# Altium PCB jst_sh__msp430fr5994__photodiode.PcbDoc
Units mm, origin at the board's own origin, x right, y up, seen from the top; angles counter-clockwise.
Board outline 56 x 30 mm, 2 copper layers (Top, Bottom), stack 0 mm thick; 17 components, 9 nets, 94 pads, 27 vias.
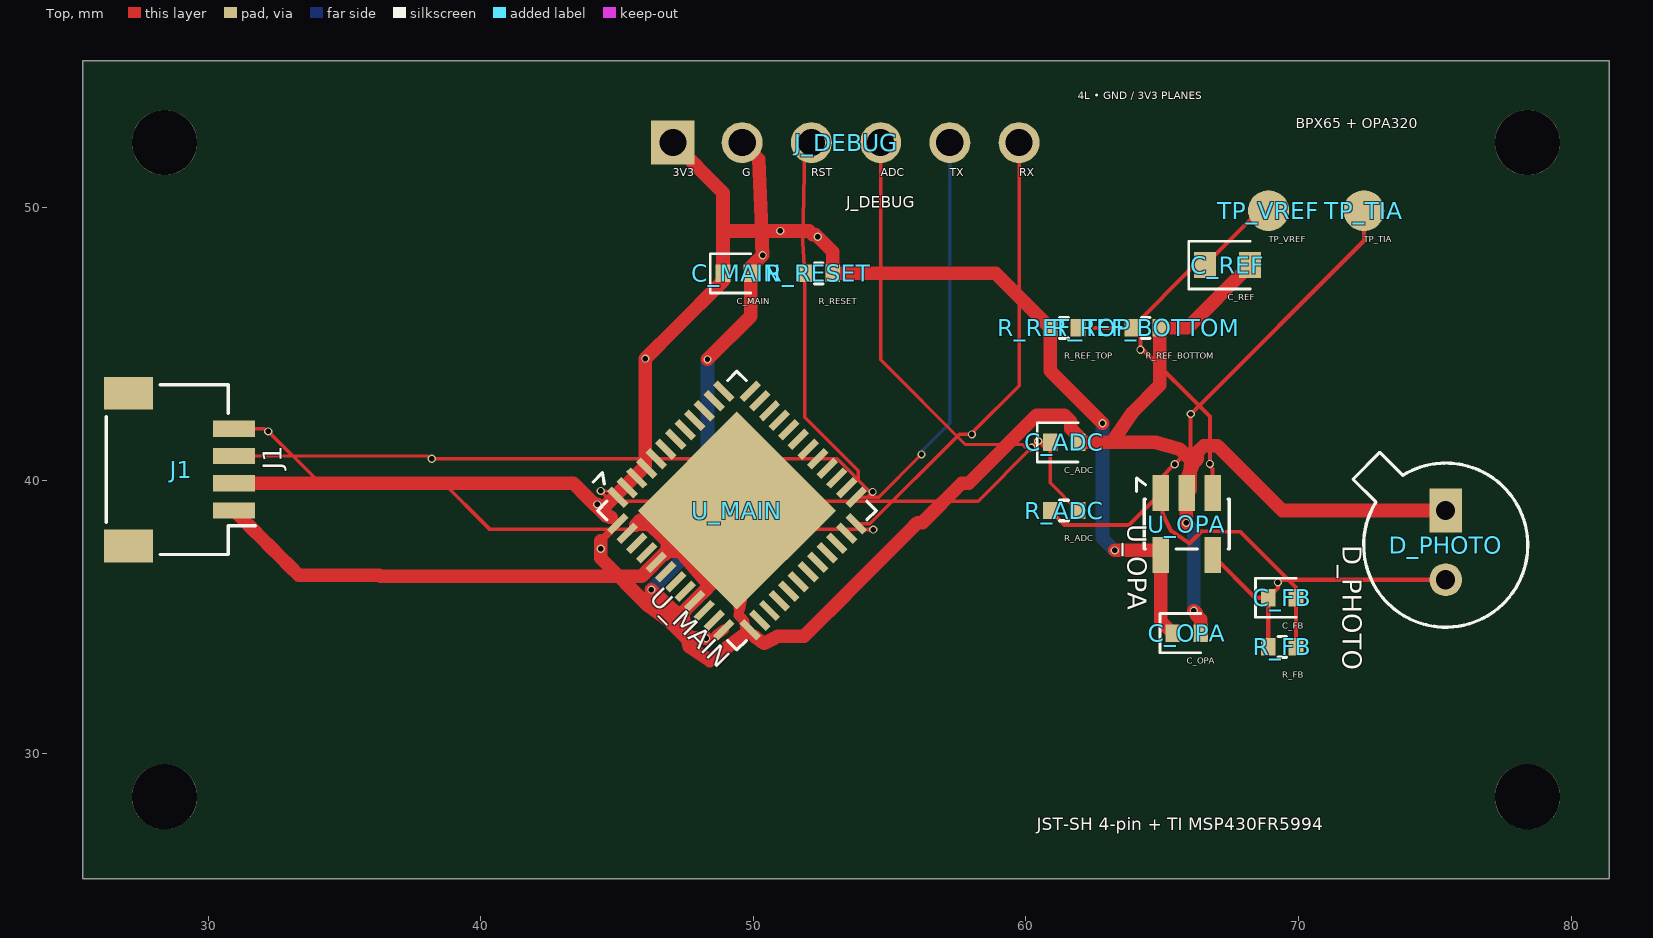
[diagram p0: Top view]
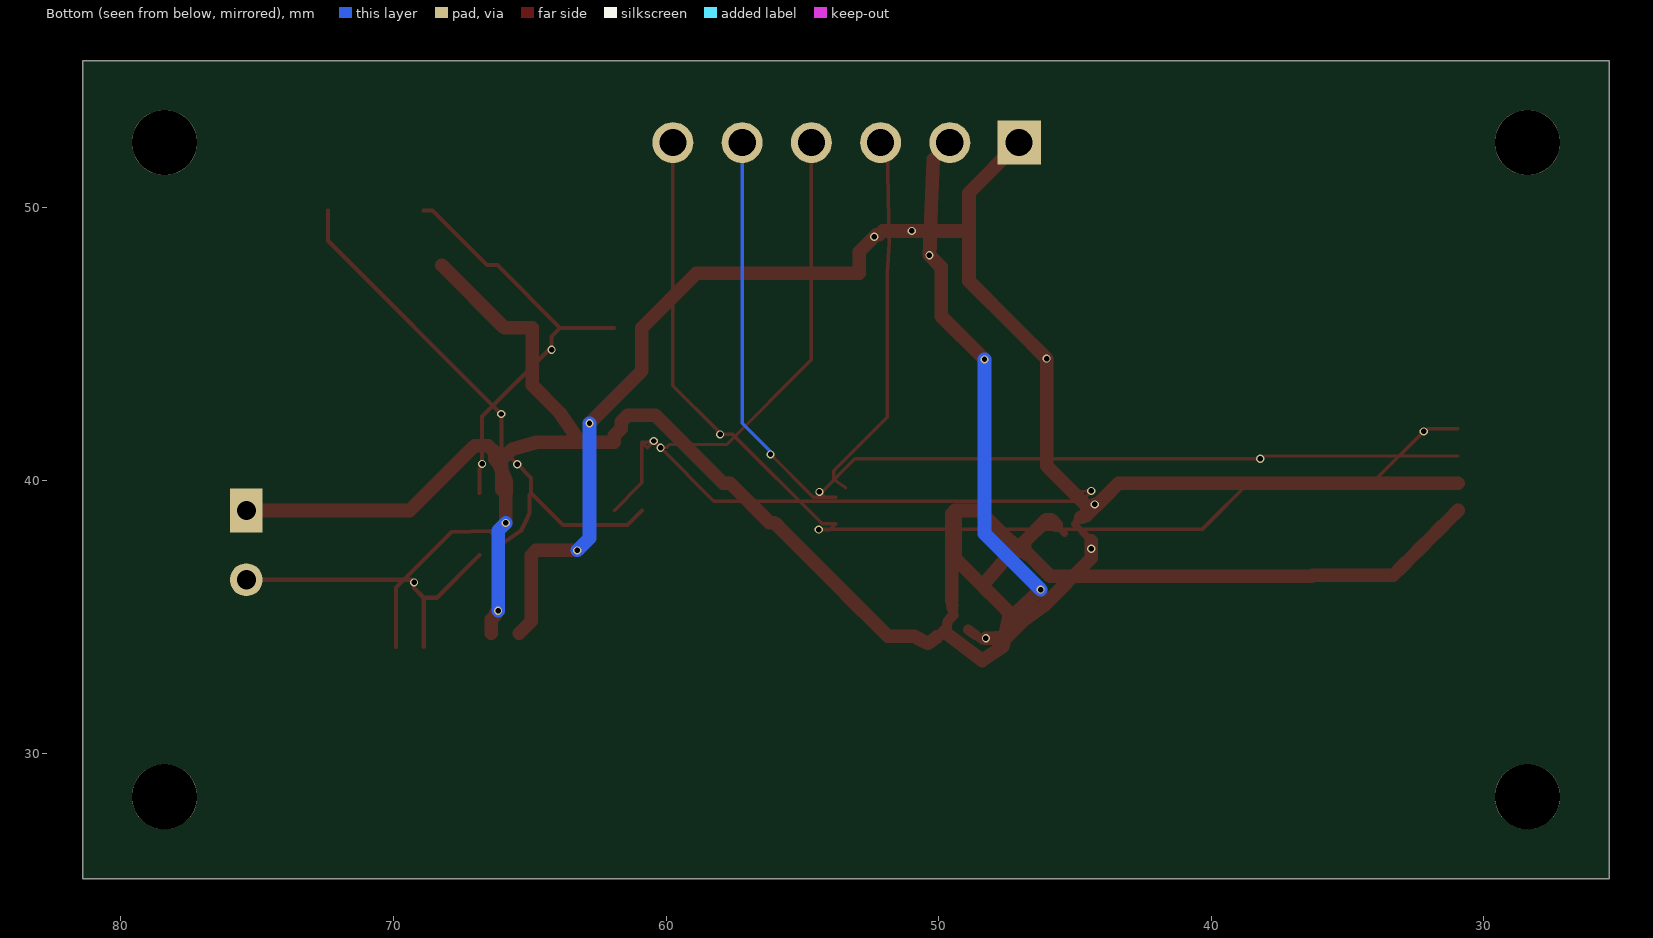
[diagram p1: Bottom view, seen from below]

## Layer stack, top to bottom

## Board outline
25.4,55.4 81.4,55.4 81.4,25.4 25.4,25.4

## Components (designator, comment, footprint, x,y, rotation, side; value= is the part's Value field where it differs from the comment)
C_ADC "" TSCIRCUIT-1.5600x0.6400mm 61.4,41.4 r0 top
C_FB "" TSCIRCUIT-1.5600x0.6400mm 69.4,35.7 r0 top
C_MAIN "" TSCIRCUIT-1.5600x0.6400mm 49.4,47.6 r0 top
C_OPA "" TSCIRCUIT-1.5600x0.6400mm 65.9,34.4 r0 top
C_REF "" TSCIRCUIT-2.4500x0.9500mm 67.4,47.9 r0 top
D_PHOTO "" TSCIRCUIT-1.2000x3.9400mm 75.4,37.73 r270 top
J1 "" TSCIRCUIT-5.5500x6.8000mm 28.95,40.4 r90 top
J_DEBUG "" TSCIRCUIT-14.2000x1.5000mm 53.4,52.4 r0 top
R_ADC "" TSCIRCUIT-1.5600x0.6400mm 61.4,38.9 r0 top
R_FB "" TSCIRCUIT-1.5600x0.6400mm 69.4,33.9 r0 top
R_REF_BOTTOM "" TSCIRCUIT-1.5600x0.6400mm 64.4,45.6 r0 top
R_REF_TOP "" TSCIRCUIT-1.5600x0.6400mm 61.4,45.6 r0 top
R_RESET "" TSCIRCUIT-1.5600x0.6400mm 52.4,47.6 r0 top
TP_TIA "" TSCIRCUIT-1.5000x1.5000mm 72.4,49.9 r0 top
TP_VREF "" TSCIRCUIT-1.5000x1.5000mm 68.9,49.9 r0 top
U_MAIN "" TSCIRCUIT-9.5459x9.5459mm 49.4,38.9 r315 top
U_OPA "" TSCIRCUIT-2.5000x3.6000mm 65.9,38.4 r270 top

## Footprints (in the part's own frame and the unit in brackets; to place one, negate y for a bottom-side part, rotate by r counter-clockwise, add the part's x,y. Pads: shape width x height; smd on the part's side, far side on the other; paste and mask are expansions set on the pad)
TSCIRCUIT-1.2000x3.9400mm [mm]
  rect 1.6x1.2 hole 0.7: 1(-1.17,0)
  round 1.2 hole 0.7: 2(1.37,0)
  silkscreen extent -3.3,-3.4 3.11,3.01
TSCIRCUIT-1.5000x1.5000mm [mm]
  round 1.5 smd: 1(0,0)
TSCIRCUIT-1.5600x0.6400mm [mm]
  rect 0.54x0.64 smd: 1(-0.51,0) 2(0.51,0)
  silkscreen extent -0.98,-0.72 0.51,0.72
TSCIRCUIT-2.4500x0.9500mm [mm]
  rect 0.8x0.95 smd: 1(-0.825,0) 2(0.825,0)
  silkscreen extent -1.43,-0.87 0.82,0.87
TSCIRCUIT-2.5000x3.6000mm [mm]
  rect 1.325x0.6 smd: 1(-1.138,-0.95) 2(-1.138,0) 3(-1.138,0.95) 4(1.137,0.95) 5(1.137,-0.95)
  silkscreen extent -1.69,-1.84 0.91,1.56
TSCIRCUIT-5.5500x6.8000mm [mm]
  rect 1.2x1.8 smd: 1(-2.8,1.875) 1(2.8,1.875)
  rect 0.6x1.55 smd: 1(-1.5,-2) 2(-0.5,-2) 3(0.5,-2) 4(1.5,-2)
  silkscreen extent -3.11,-2.77 3.11,2.69
TSCIRCUIT-9.5459x9.5459mm [mm]
  rect 0.875x0.25 smd: 1(-3.438,-2.75) 2(-3.438,-2.25) 3(-3.437,-1.75) 4(-3.437,-1.25) 5(-3.438,-0.75) 6(-3.438,-0.25) 7(-3.437,0.25) 8(-3.437,0.75) 9(-3.438,1.25) 10(-3.438,1.75) 11(-3.437,2.25) 12(-3.437,2.75) 25(3.438,2.75) 26(3.438,2.25) 27(3.438,1.75) 28(3.438,1.25) 29(3.438,0.75) 30(3.438,0.25) 31(3.438,-0.25) 32(3.438,-0.75) 33(3.438,-1.25) 34(3.438,-1.75) 35(3.438,-2.25) 36(3.438,-2.75)
  rect 0.25x0.875 smd: 13(-2.75,3.437) 14(-2.25,3.437) 15(-1.75,3.437) 16(-1.25,3.438) 17(-0.75,3.437) 18(-0.25,3.437) 19(0.25,3.437) 20(0.75,3.438) 21(1.25,3.437) 22(1.75,3.437) 23(2.25,3.437) 24(2.75,3.438) 37(2.75,-3.438) 38(2.25,-3.438) 39(1.75,-3.438) 40(1.25,-3.438) 41(0.75,-3.438) 42(0.25,-3.438) 43(-0.25,-3.438) 44(-0.75,-3.438) 45(-1.25,-3.438) 46(-1.75,-3.438) 47(-2.25,-3.438) 48(-2.75,-3.438)
  rect 5.15x5.15 smd: 49(0,0)
  silkscreen extent -4.47,-3.61 3.61,3.61
TSCIRCUIT-14.2000x1.5000mm [mm]
  rect 1.6x1.6 hole 1: 1(-6.35,0)
  round 1.5 hole 1: 2(-3.81,0) 3(-1.27,0) 4(1.27,0) 5(3.81,0) 6(6.35,0)

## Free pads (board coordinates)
  round 2.4 hole 2.4 unplated: NPTH-1(28.4,28.4) NPTH-2(78.4,52.4) NPTH-3(78.4,28.4) NPTH-4(28.4,52.4)

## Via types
v1: diameter 0.3, hole 0.2, Top to Bottom, 27 vias

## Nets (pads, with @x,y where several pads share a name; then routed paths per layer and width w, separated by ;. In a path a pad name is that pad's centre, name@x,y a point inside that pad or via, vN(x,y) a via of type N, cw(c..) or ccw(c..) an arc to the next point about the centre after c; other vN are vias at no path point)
ADC_IN: C_ADC.1 J_DEBUG.4 R_ADC.2 U_MAIN.1 | length 37
  Top w0.12: U_MAIN.1 44.811,39.6 v1(44.406,39.621) 44.412,39.588 44.426,39.588 44.771,39.244 44.783,39.244 58.244,39.244 v1(60.2,41.2) 60.217,41.217 60.4,41.4 C_ADC.1 ; J_DEBUG.4 54.67,44.429 57.777,41.322 59.878,41.322 59.983,41.217 60.183,41.217 v1(60.45,41.45) 60.69,41.2 C_ADC.1 ; R_ADC.2 60.89,39.92 C_ADC.1
GND: C_ADC.2 C_MAIN.2 C_OPA.2 C_REF.2 D_PHOTO.1 J1.1@30.95,38.9 J_DEBUG.2 R_REF_BOTTOM.2 U_MAIN.36 U_MAIN.40 U_MAIN.44 U_MAIN.47 U_MAIN.49 U_OPA.2 | length 113.1
  Top w0.25: U_MAIN.44@46.483,37.044 U_MAIN.44 ; 47.544,35.276 U_MAIN.40 U_MAIN.40@48.163,35.895 ; U_MAIN.36@49.631,34.888 U_MAIN.36@49.65,34.869 ; U_MAIN.36@49.786,34.449 U_MAIN.36 ; U_MAIN.44 46.748,37.309 U_MAIN.44 ; U_MAIN.47 45.688,38.37 U_MAIN.47
  Top w0.34: U_MAIN.44@46.483,37.044 46.483,37.067 U_MAIN.44@46.764,37.294
  Top w0.375: 49.492,35.332 49.462,35.056 49.631,34.888 ; U_MAIN.36@49.65,34.869 49.728,34.494 49.769,34.465
  Top w0.4: 49.769,34.465 U_MAIN.36@50.064,34.259
  Top w0.45: 49.492,35.332 U_MAIN.49@49.521,35.607
  Top w0.5: J1.1@30.95,38.9 31.289,38.561 31.628,38.222 31.967,37.883 32.306,37.544 32.644,37.206 32.983,36.867 33.322,36.528 33.815,36.528 34.309,36.528 34.802,36.528 35.295,36.528 35.788,36.528 36.281,36.528 36.325,36.483 45.9,36.483 46.838,37.421 46.838,37.775 46.046,38.567 45.9,38.567 45.885,38.567 45.688,38.37 45.744,38.426 45.744,38.431 46.025,38.525 46.509,38.103 46.983,37.629 46.983,37.567 46.983,37.544 46.748,37.309 46.839,37.4 47.317,37.4 48.317,36.233 48.317,36.049 48.163,35.895 ; v1(46.261,36) 47.15,35.15 47.4,35.15 ; 46.764,37.294 47.096,37.563 47.521,37.907 47.852,38.238 48.183,38.569 48.514,38.9 48.957,38.9 U_MAIN.49 ; 47.544,35.276 47.418,35.15 47.4,35.15 ; v1(48.32,44.446) 49.91,46.036 C_MAIN.2 49.91,47.836 v1(50.338,48.263) 50.32,48.704 50.303,49.145 50.286,49.586 50.269,50.027 50.252,50.467 50.234,50.908 50.217,51.349 50.2,51.79 49.895,52.095 J_DEBUG.2 ; U_MAIN.49@49.521,35.607 49.521,36.06 49.521,36.513 49.521,36.966 49.521,37.419 49.521,37.872 49.521,38.326 49.521,38.779 U_MAIN.49 ; 49.786,34.449 48.4,33.4 47.65,33.9 47.4,35.15 ; U_MAIN.36@50.064,34.259 50.4,34.025 50.649,34.156 50.897,34.287 51.378,34.287 51.859,34.287 52.207,34.634 52.554,34.982 52.902,35.329 53.249,35.676 53.596,36.024 53.944,36.371 54.291,36.719 54.639,37.066 54.986,37.413 55.333,37.761 55.681,38.108 56.028,38.456 56.206,38.456 57.65,39.9 57.9,39.9 60.4,42.4 61.4,42.4 61.65,42.15 61.65,41.9 61.9,41.65 61.9,41.4 C_ADC.2 ; v1(65.88,38.445) 65.88,39.518 U_OPA.2 ; v1(66.164,35.22) 66.244,35.14 66.244,35.081 66.41,34.915 66.41,34.657 C_OPA.2 ; C_REF.2 65.925,45.6 R_REF_BOTTOM.2 64.91,43.5 63.918,42.508 63.15,41.4 C_ADC.2 ; D_PHOTO.1 69.4,38.9 67.025,41.275 66.525,41.275 66.275,41.025 66.275,40.775 66.025,40.525 66.025,39.662 U_OPA.2 ; 47.4,35.15 49.4,37.15 U_MAIN.49 ; C_ADC.2 64.741,41.4 64.746,41.405 65.65,41.15 66.15,40.65 65.875,39.97 65.875,39.562 U_OPA.2
  Bottom w0.5: v1(46.261,36) 48.32,38.059 v1(48.32,44.446) ; v1(65.88,38.445) 66.164,38.161 v1(66.164,35.22)
MAIN_RESET: J_DEBUG.3 R_RESET.1 U_MAIN.23 | length 13.8
  Top w0.12: J_DEBUG.3 51.89,52.16 51.817,48.727 R_RESET.1 51.89,42.319 53.846,40.363 53.846,40.07 53.838,40.03 53.837,40.029 U_MAIN.23
PD_SUM: C_FB.1 D_PHOTO.2 R_FB.1 U_OPA.4 | length 11.4
  Top w0.15: U_OPA.4 68.412,35.7 C_FB.1 ; R_FB.1 C_FB.1 ; D_PHOTO.2 69.36,36.36 69.277,36.277 69.259,36.277 v1(69.244,36.262) 69.246,36.056 C_FB.1
TIA_OUT: C_FB.2 R_ADC.1 R_FB.2 TP_TIA.1 U_OPA.1 | length 27.6
  Top w0.15: R_ADC.1 61.42,38.37 63.782,38.37 U_OPA.1 ; R_FB.2 C_FB.2 69.912,36.075 67.876,38.107 66.45,38.15 66,37.7 65.325,38.15 65.1,38.6 65.011,38.813 65.011,39.476 U_OPA.1 ; TP_TIA.1 72.4,48.797 66.123,42.52 v1(66.044,42.441) 66.044,41.186 65.519,40.661 v1(65.459,40.601) 64.95,40.092 U_OPA.1
UART_MAIN_RX: J1.4 J_DEBUG.6 U_MAIN.25 | length 42.7
  Top w0.13: J1.4 32.058,41.9 32.158,41.8 v1(32.203,41.8) 33.942,40.061 38.482,40.061 40.338,38.205 54.371,38.205 54.395,38.205 v1(54.4,38.2) 53.989,38.2 U_MAIN.25 54.275,38.414 57.552,41.691 v1(58.02,41.691) 58.1,41.771 58.1,41.833 59.75,43.483 J_DEBUG.6
UART_MAIN_TX: J1.3 J_DEBUG.5 U_MAIN.24 | length 39.6
  Top w0.12: J1.3 38.058,40.9 38.158,40.8 v1(38.2,40.8) 53.072,40.8 54.331,39.54 v1(54.376,39.585) 54.177,39.386 U_MAIN.24 54.598,39.386 v1(56.17,40.958)
  Bottom w0.12: v1(56.17,40.958) 56.184,40.972 56.184,41.075 57.21,42.101 J_DEBUG.5
VCC_3V3: C_MAIN.1 C_OPA.1 J1.2 J_DEBUG.1 R_REF_TOP.1 R_RESET.2 U_MAIN.37 U_MAIN.48 U_OPA.5 | length 68.9
  Top w0.25: 44.715,38.105 U_MAIN.48 ; U_MAIN.48 44.936,38.502 U_MAIN.48
  Top w0.275: 44.4,37.789 44.712,38.101 44.715,38.105 ; 44.589,38.711 44.728,38.711 44.936,38.502 44.781,38.658
  Top w0.325: v1(48.266,34.216) 48.4,34.15 U_MAIN.37@48.657,34.337
  Top w0.382: U_MAIN.37@48.657,34.337 U_MAIN.37
  Top w0.475: v1(44.274,39.124) 44.74,38.658
  Top w0.5: J1.2 31.434,39.9 31.918,39.9 32.403,39.9 32.887,39.9 33.371,39.9 33.855,39.9 34.339,39.9 43.4,39.9 43.9,39.4 44.589,38.711 ; v1(44.274,39.124) 44.4,38.998 44.4,38.9 46.041,40.541 v1(46.041,44.473) 46.082,44.514 46.433,44.865 46.784,45.216 47.135,45.567 47.486,45.918 47.837,46.269 48.188,46.62 48.539,46.971 48.89,47.322 C_MAIN.1 ; 44.4,37.789 v1(44.4,37.5) 44.4,37.15 46.15,35.4 46.89,34.871 47.21,34.551 47.53,34.231 47.898,34.223 v1(48.266,34.216) ; 44.74,38.658 44.781,38.658 ; J_DEBUG.1 48.89,50.56 C_MAIN.1 ; v1(62.81,42.101) 60.89,44.021 R_REF_TOP.1 58.89,47.6 R_RESET.2 52.91,48.396 v1(52.361,48.945) 52.287,49.019 52.177,49.019 52.04,49.156 51.689,49.156 51.337,49.156 v1(50.985,49.156) 48.89,49.156 C_MAIN.1 ; v1(63.256,37.438) 64.775,37.438 U_OPA.5 64.95,34.84 C_OPA.1
  Bottom w0.5: v1(62.81,42.101) 62.81,37.884 v1(63.256,37.438)
VREF_0V5: C_REF.1 R_REF_BOTTOM.1 R_REF_TOP.2 TP_VREF.1 U_OPA.3 | length 16.1
  Top w0.15: R_REF_TOP.2 R_REF_BOTTOM.1 ; U_OPA.3 66.85,40.418 66.766,40.502 66.766,40.593 v1(66.751,40.608) 66.751,42.342 64.25,44.843 64.243,44.843 v1(64.2,44.8) 64.2,45.29 R_REF_BOTTOM.1 ; TP_VREF.1 68.575,49.9 C_REF.1 66.19,47.9 R_REF_BOTTOM.1
pads on no net: J1.1@27.075,37.6 J1.1@27.075,43.2 U_MAIN.2 U_MAIN.3 U_MAIN.4 U_MAIN.5 U_MAIN.6 U_MAIN.7 U_MAIN.8 U_MAIN.9 U_MAIN.10 U_MAIN.11 U_MAIN.12 U_MAIN.13 U_MAIN.14 U_MAIN.15 U_MAIN.16 U_MAIN.17 U_MAIN.18 U_MAIN.19 U_MAIN.20 U_MAIN.21 U_MAIN.22 U_MAIN.26 U_MAIN.27 U_MAIN.28 U_MAIN.29 U_MAIN.30 U_MAIN.31 U_MAIN.32 U_MAIN.33 U_MAIN.34 U_MAIN.35 U_MAIN.38 U_MAIN.39 U_MAIN.41 U_MAIN.42 U_MAIN.43 U_MAIN.45 U_MAIN.46

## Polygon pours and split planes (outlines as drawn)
GND on Mid1 (solid): 81.1,55.1 25.7,55.1 25.7,25.7 81.1,25.7
VCC_3V3 on Mid2 (solid): 81.1,55.1 25.7,55.1 25.7,25.7 81.1,25.7

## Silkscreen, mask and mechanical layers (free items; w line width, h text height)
Top Overlay:
  text "4L • GND / 3V3 PLANES" at 61.9,53.9 h0.48
  text "BPX65 + OPA320" at 69.9,52.8 h0.65
  text "JST-SH 4-pin + TI MSP430FR5994" at 60.4,27 h0.78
